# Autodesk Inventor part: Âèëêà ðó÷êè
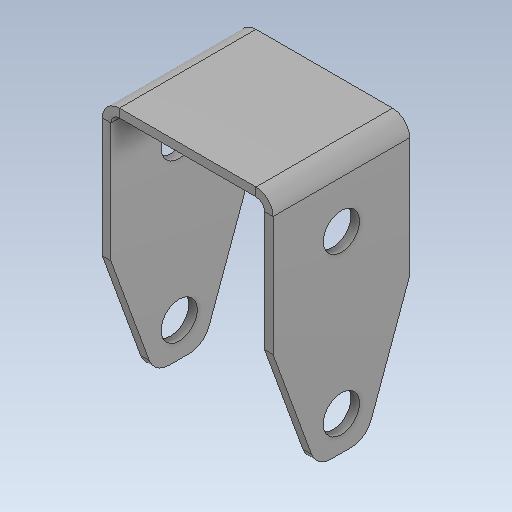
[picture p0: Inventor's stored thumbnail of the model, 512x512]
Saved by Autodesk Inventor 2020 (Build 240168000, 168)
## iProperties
Created: 1900-01
Part Number: Âèëêà ðó÷êè
Material: Générique
Document SubType Name: Modeling
Designer: bruno
Density: 1 g/cm^3
Appearance: Par défaut
Author: bruno
Revision Number: ANYUNSPECIFIED
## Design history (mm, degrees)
feature "Base1"
node "Solide1"
